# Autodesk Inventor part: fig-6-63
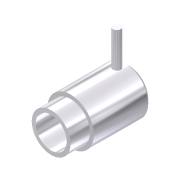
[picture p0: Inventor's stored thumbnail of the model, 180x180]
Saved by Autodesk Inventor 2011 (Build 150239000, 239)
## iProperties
Shininess: 77.0
Angle Display Precision: 2
Document Length Units: 11269
Document Angle Units: 11279
Document Time Units: 11290
Document Mass Units: 11283
Document Length Units Precision: 3
Document Angle Units Precision: 2
Compacted: True
Created: 2001-12
Part Number: fig-6-63
Document SubType Name: Modeling
Designer: Renu Muthoo
Density: 1 g/cm^3
Density: 0.0
Volumn: 0.0
Area: 0.0
PropertySet Name: Model Information
Control State: 0
Master: False
Checked Out: False
Author: Renu Muthoo
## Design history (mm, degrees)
sketch "Sketch2"
  geometry: L1 (-9.573, -4.327)-(-9.573, -5.327); L2 (-9.573, -5.327)-(-4.573, -5.327); L3 (-4.573, -5.327)-(-4.573, -6.327); L4 (-4.573, -6.327)-(9.427, -6.327); L5 (9.427, -6.327)-(10.427, -5.327); L6 (10.427, -5.327)-(10.427, -4.327); L7 (10.427, -4.327)-(-9.573, -4.327); L8 (-13.687, -0.327)-(14, -0.327)
  constraints: 16 end point, 5 parallel, 1 perpendicular, 1 vertical
  dimensions: "d9" = 20 distance of L6.end L1.start; "d10" = 5 distance of L1.end L2.end; "d11" = 12 diameter of L4 L8; "d12" = 10 diameter of L2 L8; "d13" = 8 diameter of L7 L8; "d14" = 45 deg angle of L5 L4; "d15" = 1 horizontal distance of L5.end L4.end
revolve "Revolution2" sketch "Sketch2" stored, may be unused: angle "d16" = 90 deg
workplane "Work Plane1"
workplane "Work Plane2"
sketch "Sketch3"
  geometry: L1 (-4, 8)-(4, 8) reference; C1 r 1 at (-0.098, 5)
  constraints: 1 centre point
  dimensions: "d18" = 3 distance from line of L1 C1.centre; "d19" = 2 diameter of C1
extrude "Extrusion1" join sketch "Sketch3" distance "d20" = 10; taper "d21" = 0 deg
body "Solid1"
other parameters: "d17" = -1
